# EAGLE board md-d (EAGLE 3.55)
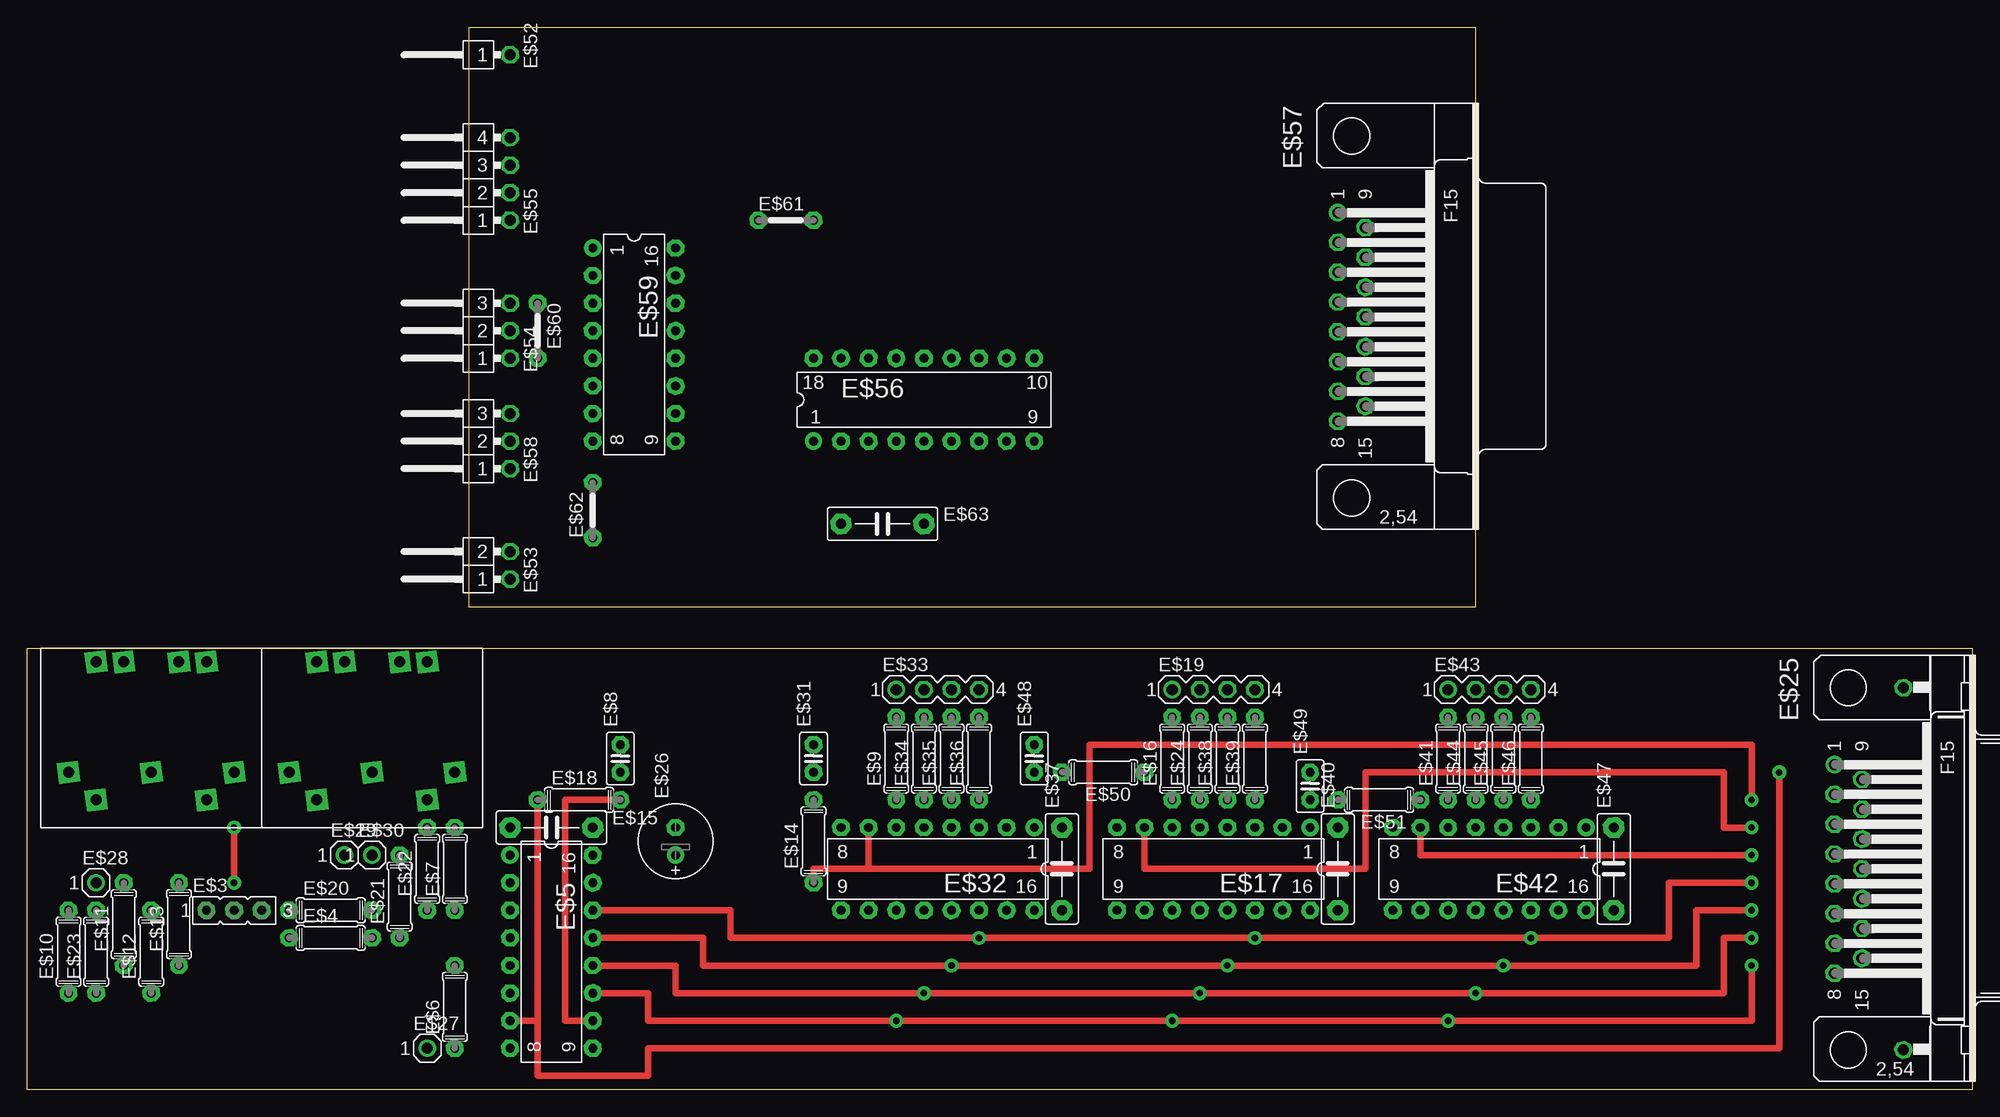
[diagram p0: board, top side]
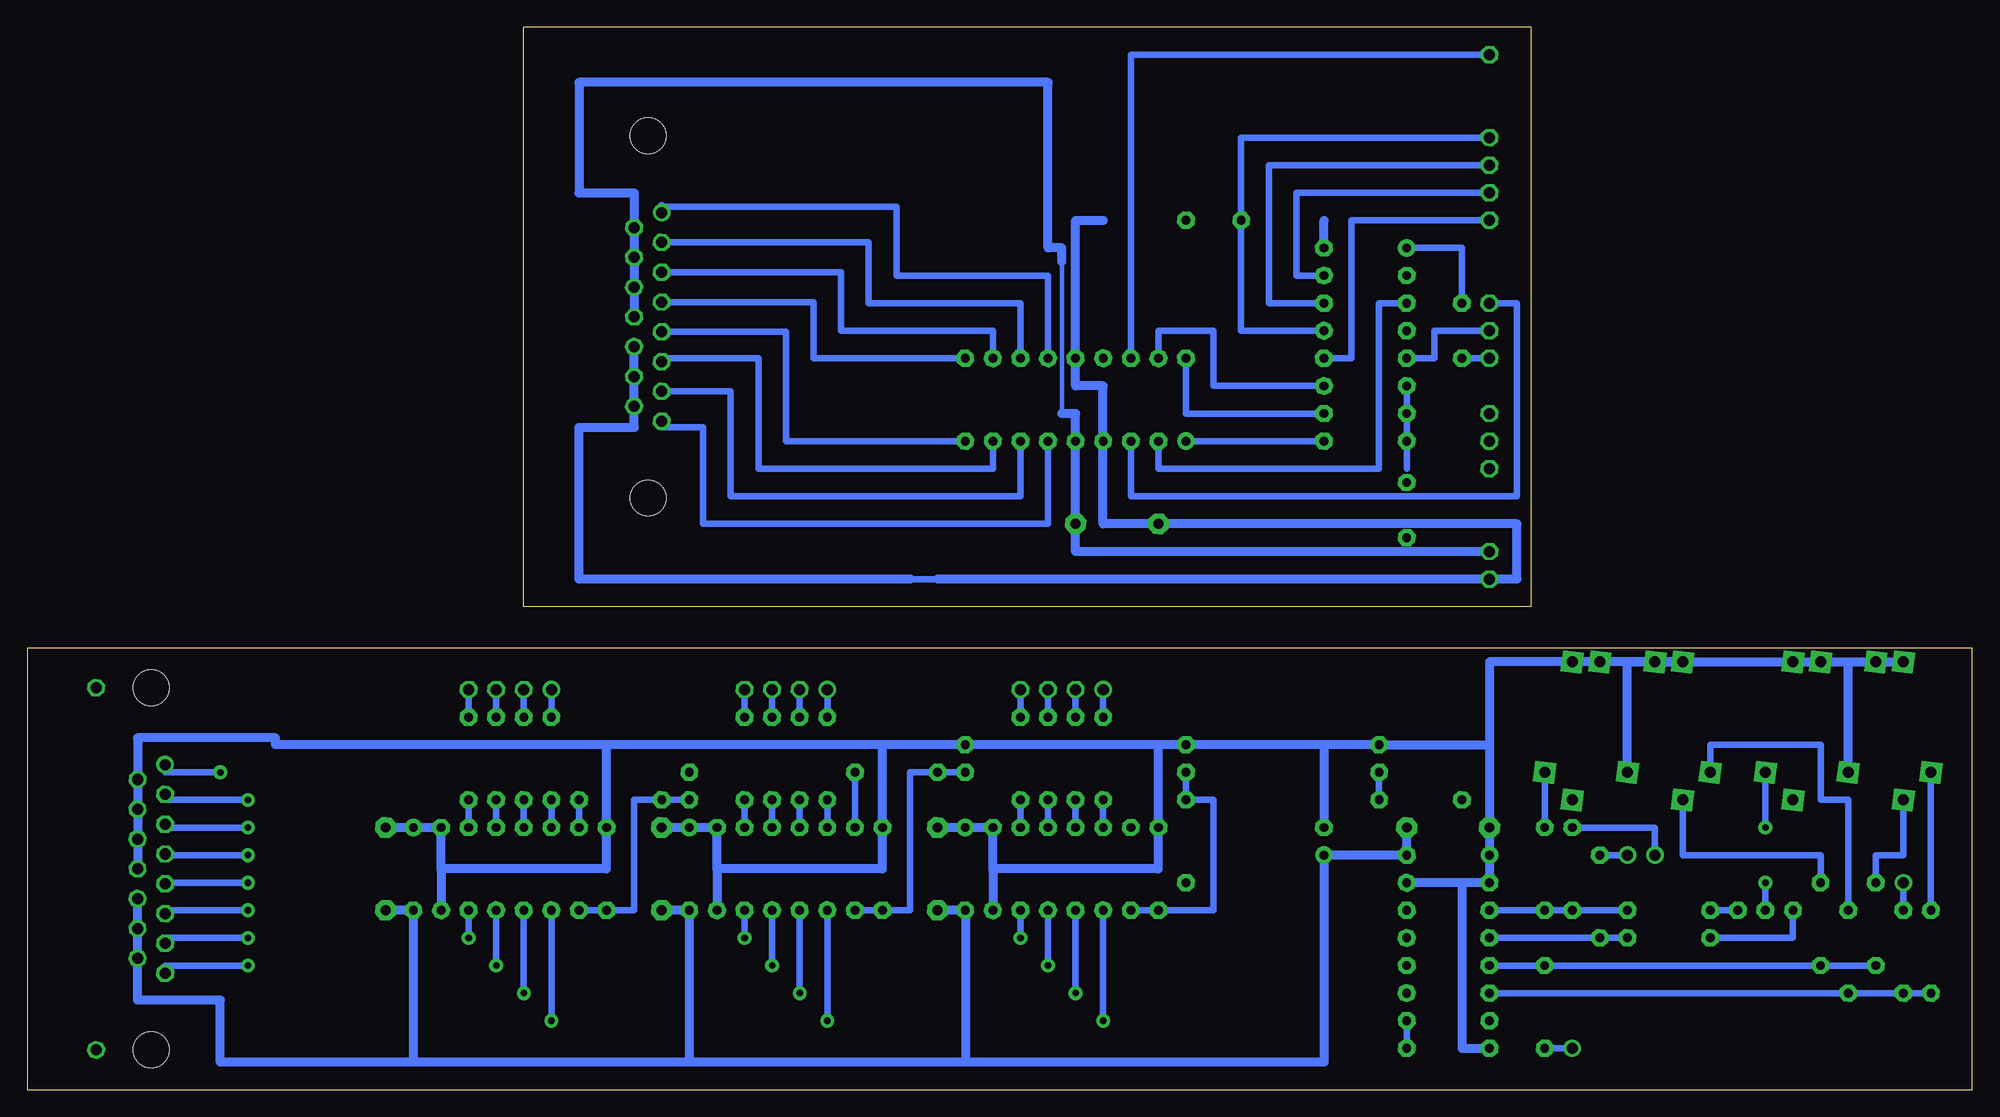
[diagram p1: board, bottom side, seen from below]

Size 179.07 x 97.79 mm. Coordinates in mm from the lower left corner, seen from the top.
Outline: 0,40.64 179.07,40.64 179.07,0 0,0 0,40.64
Outline: 40.64,97.79 133.35,97.79 133.35,44.45 40.64,44.45 40.64,97.79
Copper layers used: Top, Bottom

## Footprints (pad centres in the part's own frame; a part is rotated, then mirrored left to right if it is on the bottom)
_PCB = drill 1.016 pad 1.93 square:  -7.62,10.16;  -5.08,10.16;  0,10.16;  2.54,10.16;  -2.54,0;  -7.62,-2.54;  -10.16,0;  2.54,-2.54;  5.08,0
03-1 = drill 0.813 pad 1.6 octagon:  -2.54,0;  0,0;  2.54,0
07/7 = drill 0.813 pad 1.6 octagon:  -3.81,0;  3.81,0
L16 = drill 0.813 pad 1.6 round:  -8.89,-3.81 | drill 0.813 pad 1.6 octagon:  -6.35,-3.81;  -3.81,-3.81;  -1.27,-3.81;  1.27,-3.81;  3.81,-3.81;  6.35,-3.81;  8.89,-3.81;  8.89,3.81;  6.35,3.81;  3.81,3.81;  1.27,3.81;  -1.27,3.81;  -3.81,3.81;  -6.35,3.81;  -8.89,3.81
,5-2 = drill 0.813 pad 1.6 octagon:  -1.27,0;  1.27,0
,5B3 = drill 0.914 pad 1.905 octagon:  -3.81,0;  3.81,0
04-1 = drill 1.016 pad 1.6 round:  -3.81,0 | drill 1.016 pad 1.6 octagon:  -1.27,0;  1.27,0;  3.81,0
5H = drill 1.016 pad 1.6 round:  -9.601,-1.27 | drill 1.016 pad 1.6 octagon:  -6.858,-1.27;  -4.115,-1.27;  -1.372,-1.27;  1.372,-1.27;  4.115,-1.27;  6.858,-1.27;  9.601,-1.27;  -8.23,1.27;  -5.486,1.27;  -2.743,1.27;  0,1.27;  2.743,1.27;  5.486,1.27;  8.23,1.27;  -16.662,5.08;  16.662,5.08 | hole 3.302: -16.662,0; 16.662,0
,5-7 = drill 0.813 pad 1.6 octagon:  1.27,0 | drill 0.813 pad 1.6 round:  -1.27,0
01-1 = drill 1.016 pad 1.6 round:  0,0
01-1W = drill 1.016 pad 1.6 octagon:  0,0
02-1W = drill 1.016 pad 1.6 octagon:  2.54,0;  0,0
03-1W = drill 1.016 pad 1.6 octagon:  5.08,0;  2.54,0;  0,0
04-1W = drill 1.016 pad 1.6 octagon:  7.62,0;  5.08,0;  2.54,0;  0,0
L18 = drill 0.813 pad 1.6 round:  -10.16,-3.81 | drill 0.813 pad 1.6 octagon:  -7.62,-3.81;  -5.08,-3.81;  -2.54,-3.81;  0,-3.81;  2.54,-3.81;  5.08,-3.81;  7.62,-3.81;  10.16,-3.81;  10.16,3.81;  7.62,3.81;  5.08,3.81;  2.54,3.81;  0,3.81;  -2.54,3.81;  -5.08,3.81;  -7.62,3.81;  -10.16,3.81
5H' = drill 1.016 pad 1.6 round:  -9.601,-1.27 | drill 1.016 pad 1.6 octagon:  -6.858,-1.27;  -4.115,-1.27;  -1.372,-1.27;  1.372,-1.27;  4.115,-1.27;  6.858,-1.27;  9.601,-1.27;  -8.23,1.27;  -5.486,1.27;  -2.743,1.27;  0,1.27;  2.743,1.27;  5.486,1.27;  8.23,1.27 | hole 3.302: -16.662,0; 16.662,0
 = drill 0.813 pad 1.6 octagon:  -2.54,0;  2.54,0

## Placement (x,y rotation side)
E$1  [_PCB]  13.97,29.21 0 top
E$2  [_PCB]  34.29,29.21 0 top
E$3  [03-1]  19.05,16.51 0 top
E$4  220  [07/7]  27.94,13.97 0 top
E$5  [L16]  48.26,12.7 270 top
E$6  220  [07/7]  39.37,7.62 90 top
E$7  220  [07/7]  39.37,20.32 90 top
E$8  1n  [,5-2]  54.61,30.48 90 top
E$9  220  [07/7]  80.01,30.48 90 top
E$10  220  [07/7]  3.81,12.7 90 top
E$11  220  [07/7]  8.89,15.24 90 top
E$12  220  [07/7]  11.43,12.7 90 top
E$13  220  [07/7]  13.97,15.24 90 top
E$14  560  [07/7]  72.39,22.86 90 top
E$15  0.1  [,5B3]  48.26,24.13 0 top
E$16  220  [07/7]  105.41,30.48 90 top
E$17  [L16]  109.22,20.32 180 top
E$18  560  [07/7]  50.8,26.67 0 top
E$19  [04-1]  109.22,36.83 0 top
E$20  220  [07/7]  27.94,16.51 0 top
E$21  220  [07/7]  34.29,17.78 90 top
E$22  220  [07/7]  36.83,20.32 90 top
E$23  220  [07/7]  6.35,12.7 90 top
E$24  220  [07/7]  107.95,30.48 90 top
E$25  [5H]  167.64,20.32 270 top
E$26  100u/16V  [,5-7]  59.69,22.86 90 top
E$27  [01-1]  36.83,3.81 0 top
E$28  [01-1]  6.35,19.05 0 top
E$29  [01-1]  29.21,21.59 0 top
E$30  [01-1]  31.75,21.59 0 top
E$31  1n  [,5-2]  72.39,30.48 90 top
E$32  [L16]  83.82,20.32 180 top
E$33  [04-1]  83.82,36.83 0 top
E$34  220  [07/7]  82.55,30.48 90 top
E$35  220  [07/7]  85.09,30.48 90 top
E$36  220  [07/7]  87.63,30.48 90 top
E$37  0.1  [,5B3]  95.25,20.32 90 top
E$38  220  [07/7]  110.49,30.48 90 top
E$39  220  [07/7]  113.03,30.48 90 top
E$40  0.1  [,5B3]  120.65,20.32 90 top
E$41  220  [07/7]  130.81,30.48 90 top
E$42  [L16]  134.62,20.32 180 top
E$43  [04-1]  134.62,36.83 0 top
E$44  220  [07/7]  133.35,30.48 90 top
E$45  220  [07/7]  135.89,30.48 90 top
E$46  220  [07/7]  138.43,30.48 90 top
E$47  0.1  [,5B3]  146.05,20.32 90 top
E$48  1n  [,5-2]  92.71,30.48 90 top
E$49  1n  [,5-2]  118.11,27.94 90 top
E$50  560  [07/7]  99.06,29.21 180 top
E$51  560  [07/7]  124.46,26.67 180 top
E$52  [01-1W]  44.45,95.25 90 top
E$53  [02-1W]  44.45,46.99 90 top
E$54  [03-1W]  44.45,67.31 90 top
E$55  [04-1W]  44.45,80.01 90 top
E$56  PIC16F84/10MHz  [L18]  82.55,63.5 0 top
E$57  SUB-D 15p F  [5H']  121.92,71.12 270 top
E$58  [03-1W]  44.45,57.15 90 top
E$59  4051  [L16]  55.88,68.58 270 top
E$60  []  46.99,69.85 270 top
E$61  []  69.85,80.01 0 top
E$62  GND  []  52.07,53.34 90 top
E$63  0.1  [,5B3]  78.74,52.07 0 top

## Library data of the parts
E$1 E$2 = con-din
E$3 = CON-LSTA
E$4 E$6 E$7 E$9-E$14 E$16 E$18 E$20-E$24 E$34-E$36 E$38 E$39 E$41 E$44-E$46 E$50 E$51 = r
E$5 E$17 E$32 E$42 = 74XX
E$8 E$15 E$31 E$37 E$40 E$47-E$49 E$63 = CAP
E$19 E$27-E$30 E$33 E$43 = CON-LSTB
E$25 = SUBD-A
E$26 = POLCAP
E$52-E$55 E$58 = con-lstb
E$56 = pic
E$57 = subd
E$59 = 40XX
E$60-E$62 = JUMPER

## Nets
CONT: E$5. E$6. E$11. E$13.
CONT1: E$1. E$11.
CONT2: E$2. E$13.
GND: E$1. E$2. E$5. E$8. E$15. E$17. E$25. E$26. E$31. E$32. E$37. E$40. E$42. E$47. E$48.
GND1: E$53. E$56. E$57. E$62. E$63.
IN0: E$5. E$17. E$25. E$32. E$42.
IN1: E$5. E$17. E$25. E$32. E$42.
IN2: E$5. E$17. E$25. E$32. E$42.
IN3: E$5. E$17. E$25. E$32. E$42.
S$1: E$55. E$59.
S$2: E$25. E$42. E$51.
S$3: E$42. E$49. E$51.
S$4: E$55. E$59.
S$5: E$9. E$32.
S$6: E$32. E$34.
S$7: E$32. E$35.
S$8: E$55. E$59.
S$9: E$32. E$36.
S$10: E$33. E$36.
S$11: E$33. E$35.
S$12: E$33. E$34.
S$13: E$9. E$33.
S$14: E$14. E$31. E$32.
S$15: E$55. E$59.
S$16: E$5. E$18. E$25.
S$17: E$17. E$25. E$50.
S$18: E$59. E$61.
S$19: E$56. E$57.
S$20: E$56. E$57.
S$21: E$16. E$17.
S$22: E$56. E$57.
S$23: E$17. E$24.
S$24: E$17. E$38.
S$25: E$17. E$39.
S$26: E$19. E$39.
S$27: E$19. E$38.
S$28: E$19. E$24.
S$29: E$16. E$19.
S$30: E$17. E$48. E$50.
S$31: E$56. E$57.
S$32: E$14. E$25. E$32.
S$33: E$56. E$57.
S$34: E$5. E$8. E$18.
S$35: E$56. E$57.
S$36: E$56. E$57.
S$37: E$41. E$42.
S$38: E$42. E$44.
S$39: E$42. E$45.
S$40: E$42. E$46.
S$41: E$43. E$46.
S$42: E$43. E$45.
S$43: E$43. E$44.
S$44: E$41. E$43.
S$45: E$59. E$62.
S$46: E$54. E$60.
S$47: E$59. E$60.
S$48: E$2. E$12.
S$49: E$1. E$3.
S$50: E$54. E$56.
S$51: E$3. E$4.
S$52: E$3. E$20.
S$53: E$5. E$7. E$20. E$22.
S$54: E$2. E$7.
S$55: E$22. E$29.
S$56: E$21. E$30.
S$57: E$4. E$5. E$21.
S$58: E$56. E$59.
S$59: E$23. E$28.
S$60: E$1. E$10.
S$61: E$56. E$59.
S$62: E$56. E$59.
S$63: E$6. E$27.
S$64: E$56. E$59.
S$65: E$54. E$59.
S$66: E$56. E$57.
S$67: E$52. E$56.
STRT_STP: E$5. E$10. E$12. E$23.
VCC: E$5. E$15. E$17. E$25. E$26. E$32. E$37. E$40. E$42. E$47.
VCC1: E$53. E$56. E$57. E$61. E$63.

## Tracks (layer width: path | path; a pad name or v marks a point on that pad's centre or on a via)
CONT
  Bottom 0.61: 44.45,11.43 E$6. 13.97,11.43 8.89,11.43
CONT1
  Bottom 0.61: E$11. 8.89,21.59 6.35,21.59 6.35,26.67
CONT2
  Bottom 0.61: E$13. 13.97,21.59 26.67,21.59 26.67,26.67
GND
  Bottom 0.61: 133.35,31.75 156.21,31.75 | 44.45,19.05 44.45,21.59 44.45,24.13 | 36.83,39.37 34.29,39.37 31.75,39.37 | 29.21,39.37 26.67,39.37 16.51,39.37 13.97,39.37 | 8.89,39.37 6.35,39.37
  Bottom 0.813: 44.45,3.81 46.99,3.81 46.99,19.05 | 46.99,19.05 52.07,19.05 | 46.99,19.05 44.45,19.05 44.45,21.59 44.45,24.13 44.45,31.75 | 168.91,20.32 168.91,23.06 168.91,25.81 168.91,29.21 | 168.91,29.21 168.91,28.55 | 168.91,29.21 168.91,32.39 156.21,32.39 156.21,31.75 125.73,31.75 | 59.69,31.75 E$8. 44.45,31.75 | 59.69,31.75 59.69,24.13 | 59.69,31.75 E$31. 74.93,31.75 | 74.93,31.75 E$48. 100.33,31.75 | 125.73,31.75 133.35,31.75 | 44.45,31.75 44.45,39.37 36.83,39.37 34.29,39.37 29.21,39.37 | 31.75,29.21 31.75,39.37 29.21,39.37 | 29.21,39.37 26.67,39.37 | 26.67,39.37 16.51,39.37 13.97,39.37 11.43,39.37 | 11.43,39.37 8.89,39.37 6.35,39.37 | 11.43,29.21 11.43,39.37 | 26.67,39.37 29.21,39.37 | 100.33,31.75 125.73,31.75 | 90.17,20.32 90.17,16.51 | 90.17,20.32 90.17,24.13 92.71,24.13 E$37. | 90.17,20.32 74.93,20.32 74.93,24.13 74.93,31.75 | 115.57,20.32 115.57,16.51 | 115.57,20.32 115.57,24.13 118.11,24.13 E$40. | 115.57,20.32 100.33,20.32 100.33,24.13 100.33,31.75 | 140.97,20.32 140.97,16.51 | 140.97,20.32 140.97,24.13 143.51,24.13 E$47. | 140.97,20.32 125.73,20.32 125.73,24.13 125.73,31.75
GND1
  Bottom 0.406: 83.82,62.23 83.82,76.2
  Bottom 0.813: 123.19,71.12 123.19,73.86 123.19,76.61 123.19,79.35 123.19,82.55 128.27,82.55 128.27,92.71 85.09,92.71 85.09,77.47 83.82,77.47 83.82,76.2 | 83.82,62.23 82.55,62.23 82.55,59.69 E$63. 82.55,49.53 52.07,49.53 44.45,49.53 49.53,49.53
IN0  (via drill 0.61 pad 1.27)
  Top 0.61: v158.75,11.43 158.75,6.35 v130.81,6.35 v105.41,6.35 v80.01,6.35 57.15,6.35 57.15,8.89 52.07,8.89
  Bottom 0.61: v105.41,6.35 105.41,16.51 | v130.81,6.35 130.81,16.51 | 166.37,10.72 166.37,11.43 v158.75,11.43 | v80.01,6.35 80.01,16.51
IN1  (via drill 0.61 pad 1.27)
  Top 0.61: v158.75,13.97 156.21,13.97 156.21,8.89 v133.35,8.89 v107.95,8.89 v82.55,8.89 59.69,8.89 59.69,11.43 52.07,11.43
  Bottom 0.61: v107.95,8.89 107.95,16.51 | v133.35,8.89 133.35,16.51 | 166.37,13.46 166.37,13.97 v158.75,13.97 | v82.55,8.89 82.55,16.51
IN2  (via drill 0.61 pad 1.27)
  Top 0.61: 52.07,13.97 62.23,13.97 62.23,11.43 v85.09,11.43 v110.49,11.43 v135.89,11.43 153.67,11.43 153.67,16.51 v158.75,16.51
  Bottom 0.61: v110.49,11.43 110.49,16.51 | v135.89,11.43 135.89,16.51 | 166.37,16.21 166.37,16.51 v158.75,16.51 | v85.09,11.43 85.09,16.51
IN3  (via drill 0.61 pad 1.27)
  Top 0.61: v158.75,19.05 151.13,19.05 151.13,13.97 v138.43,13.97 v113.03,13.97 v87.63,13.97 64.77,13.97 64.77,16.51 52.07,16.51
  Bottom 0.61: v87.63,13.97 87.63,16.51 | v113.03,13.97 113.03,16.51 | v138.43,13.97 138.43,16.51 | 166.37,18.95 166.37,19.05 v158.75,19.05
S$1
  Bottom 0.61: E$55. 57.15,80.01 57.15,67.31 59.69,67.31
S$2  (via drill 0.61 pad 1.27)
  Top 0.61: 128.27,24.13 128.27,21.59 v158.75,21.59
  Bottom 0.61: 166.37,21.69 166.37,21.59 v158.75,21.59 | 128.27,24.13 128.27,26.67
S$3
  Bottom 0.61: 118.11,26.67 E$51. 123.19,26.67 123.19,16.51 125.73,16.51 128.27,16.51
S$4
  Bottom 0.61: 59.69,69.85 67.31,69.85 67.31,87.63 44.45,87.63
S$5
  Bottom 0.61: 80.01,24.13 80.01,26.67
S$6
  Bottom 0.61: 82.55,24.13 82.55,26.67
S$7
  Bottom 0.61: 85.09,24.13 85.09,26.67
S$8
  Bottom 0.61: 44.45,85.09 64.77,85.09 64.77,72.39 59.69,72.39
S$9
  Bottom 0.61: 87.63,24.13 87.63,26.67
S$10
  Bottom 0.61: E$36. E$33.
S$11
  Bottom 0.61: E$35. 85.09,36.83
S$12
  Bottom 0.61: E$34. 82.55,36.83
S$13
  Bottom 0.61: E$9. 80.01,36.83
S$14
  Bottom 0.61: 77.47,16.51 74.93,16.51 69.85,16.51 69.85,26.67 E$14. 72.39,29.21
S$15
  Bottom 0.61: 59.69,74.93 62.23,74.93 62.23,82.55 44.45,82.55
S$16  (via drill 0.61 pad 1.27)
  Top 0.61: v161.29,29.21 161.29,3.81 57.15,3.81 57.15,1.27 46.99,1.27 46.99,6.35 | 46.99,6.35 44.45,6.35 | 46.99,6.35 46.99,26.67
  Bottom 0.61: 166.37,29.92 166.37,29.21 v161.29,29.21
S$17  (via drill 0.61 pad 1.27)
  Top 0.61: v158.75,24.13 156.21,24.13 156.21,29.21 123.19,29.21 123.19,20.32 102.87,20.32 102.87,24.13
  Bottom 0.61: 166.37,24.43 166.37,24.13 v158.75,24.13 | 102.87,24.13 102.87,29.21
S$18
  Bottom 0.813: E$59. 59.69,80.01
S$19
  Bottom 0.61: 120.65,77.98 101.6,77.98 101.6,72.39 87.63,72.39 87.63,67.31
S$20
  Bottom 0.61: 120.65,75.23 104.14,75.23 104.14,69.85 90.17,69.85 90.17,67.31
S$21
  Bottom 0.61: 105.41,24.13 105.41,26.67
S$22
  Bottom 0.61: 120.65,72.49 106.68,72.49 106.68,67.31 92.71,67.31
S$23
  Bottom 0.61: 107.95,24.13 107.95,26.67
S$24
  Bottom 0.61: 110.49,24.13 110.49,26.67
S$25
  Bottom 0.61: 113.03,24.13 113.03,26.67
S$26
  Bottom 0.61: E$39. E$19.
S$27
  Bottom 0.61: E$38. 110.49,36.83
S$28
  Bottom 0.61: E$24. 107.95,36.83
S$29
  Bottom 0.61: E$16. 105.41,36.83
S$30
  Bottom 0.61: 102.87,16.51 100.33,16.51 97.79,16.51 97.79,29.21 E$50. 92.71,29.21
S$31
  Bottom 0.61: 120.65,69.75 109.22,69.75 109.22,59.69 92.71,59.69
S$32  (via drill 0.61 pad 1.27)
  Top 0.61: 77.47,20.32 77.47,24.13 | 77.47,20.32 97.79,20.32 97.79,31.75 158.75,31.75 v158.75,26.67 | 72.39,19.05 72.39,20.32 77.47,20.32
  Bottom 0.61: 166.37,27.18 166.37,26.67 v158.75,26.67
S$33
  Bottom 0.61: 90.17,59.69 90.17,57.15 111.76,57.15 111.76,67.31 120.65,67.31 120.65,67
S$34
  Top 0.61: 52.07,6.35 49.53,6.35 49.53,26.67 E$18.
  Bottom 0.61: E$18. 54.61,29.21 | 52.07,3.81 52.07,6.35
S$35
  Bottom 0.61: 120.65,64.26 114.3,64.26 114.3,54.61 87.63,54.61 87.63,59.69
S$36
  Bottom 0.406: 120.65,60.96 120.65,61.52
  Bottom 0.61: 85.09,59.69 85.09,52.07 116.84,52.07 116.84,60.96 120.65,60.96
S$37
  Bottom 0.61: 130.81,24.13 130.81,26.67
S$38
  Bottom 0.61: 133.35,24.13 133.35,26.67
S$39
  Bottom 0.61: 135.89,24.13 135.89,26.67
S$40
  Bottom 0.61: 138.43,24.13 138.43,26.67
S$41
  Bottom 0.61: E$46. E$43.
S$42
  Bottom 0.61: E$45. 135.89,36.83
S$43
  Bottom 0.61: E$44. 133.35,36.83
S$44
  Bottom 0.61: E$41. 130.81,36.83
S$45
  Bottom 0.61: 52.07,57.15 52.07,59.69 52.07,62.23 52.07,64.77
S$46
  Bottom 0.61: E$54. E$60.
S$47
  Bottom 0.61: 46.99,72.39 46.99,77.47 52.07,77.47
S$48
  Bottom 0.61: E$12. 11.43,26.67 13.97,26.67 13.97,31.75 24.13,31.75 24.13,29.21
S$49  (via drill 0.61 pad 1.27)
  Top 0.61: v19.05,19.05 v19.05,24.13
  Bottom 0.61: 19.05,16.51 v19.05,19.05 | v19.05,24.13 E$1.
S$50
  Bottom 0.61: 44.45,72.39 41.91,72.39 41.91,54.61 77.47,54.61 77.47,59.69
S$51
  Bottom 0.61: 16.51,16.51 16.51,13.97 24.13,13.97
S$52
  Bottom 0.61: E$3. 24.13,16.51
S$53
  Bottom 0.61: E$20. 36.83,16.51 39.37,16.51 44.45,16.51
S$54
  Bottom 0.61: E$7. E$2.
S$55
  Bottom 0.61: E$22. 29.21,24.13 E$29.
S$56
  Bottom 0.61: E$30. E$21.
S$57
  Bottom 0.61: E$4. 34.29,13.97 44.45,13.97
S$58
  Bottom 0.61: 74.93,59.69 74.93,57.15 54.61,57.15 54.61,72.39 52.07,72.39
S$59
  Bottom 0.61: E$23. E$28.
S$60
  Bottom 0.61: E$10. 3.81,29.21
S$61
  Bottom 0.61: 59.69,64.77 69.85,64.77 69.85,69.85 74.93,69.85 74.93,67.31
S$62
  Bottom 0.61: E$56. 72.39,62.23 59.69,62.23
S$63
  Bottom 0.61: E$27. 39.37,3.81
S$64
  Bottom 0.61: 59.69,59.69 72.39,59.69
S$65
  Bottom 0.61: 44.45,69.85 49.53,69.85 49.53,67.31 52.07,67.31
S$66
  Bottom 0.61: 85.09,67.31 85.09,74.93 99.06,74.93 99.06,81.28 120.65,81.28
  Bottom 0.813: 120.65,80.72 120.65,81.28
S$67
  Bottom 0.61: E$52. 77.47,95.25 77.47,67.31
STRT_STP
  Bottom 0.61: 3.81,8.89 6.35,8.89 11.43,8.89 44.45,8.89
VCC
  Bottom 0.61: E$26. E$5.
  Bottom 0.813: 146.05,16.51 E$42. 143.51,2.54 | 120.65,16.51 E$17. 118.11,2.54 | 95.25,16.51 E$32. 92.71,2.54 | E$15. E$5. E$26. 59.69,2.54 92.71,2.54 | 168.91,14.83 168.91,15.24 | 168.91,14.83 168.91,12.09 168.91,8.25 161.29,8.25 161.29,2.54 143.51,2.54 | 168.91,17.78 168.91,17.58 168.91,14.83 | 118.11,2.54 143.51,2.54 | 92.71,2.54 118.11,2.54
VCC1
  Bottom 0.61: 95.25,46.99 97.79,46.99
  Bottom 0.813: 95.25,46.99 E$53. 41.91,46.99 41.91,52.07 74.93,52.07 80.01,52.07 80.01,59.69 80.01,64.77 82.55,64.77 82.55,67.31 82.55,80.01 80.01,80.01 | 123.19,68.38 123.19,65.63 E$57. 123.19,60.96 128.27,60.96 128.27,46.99 97.79,46.99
